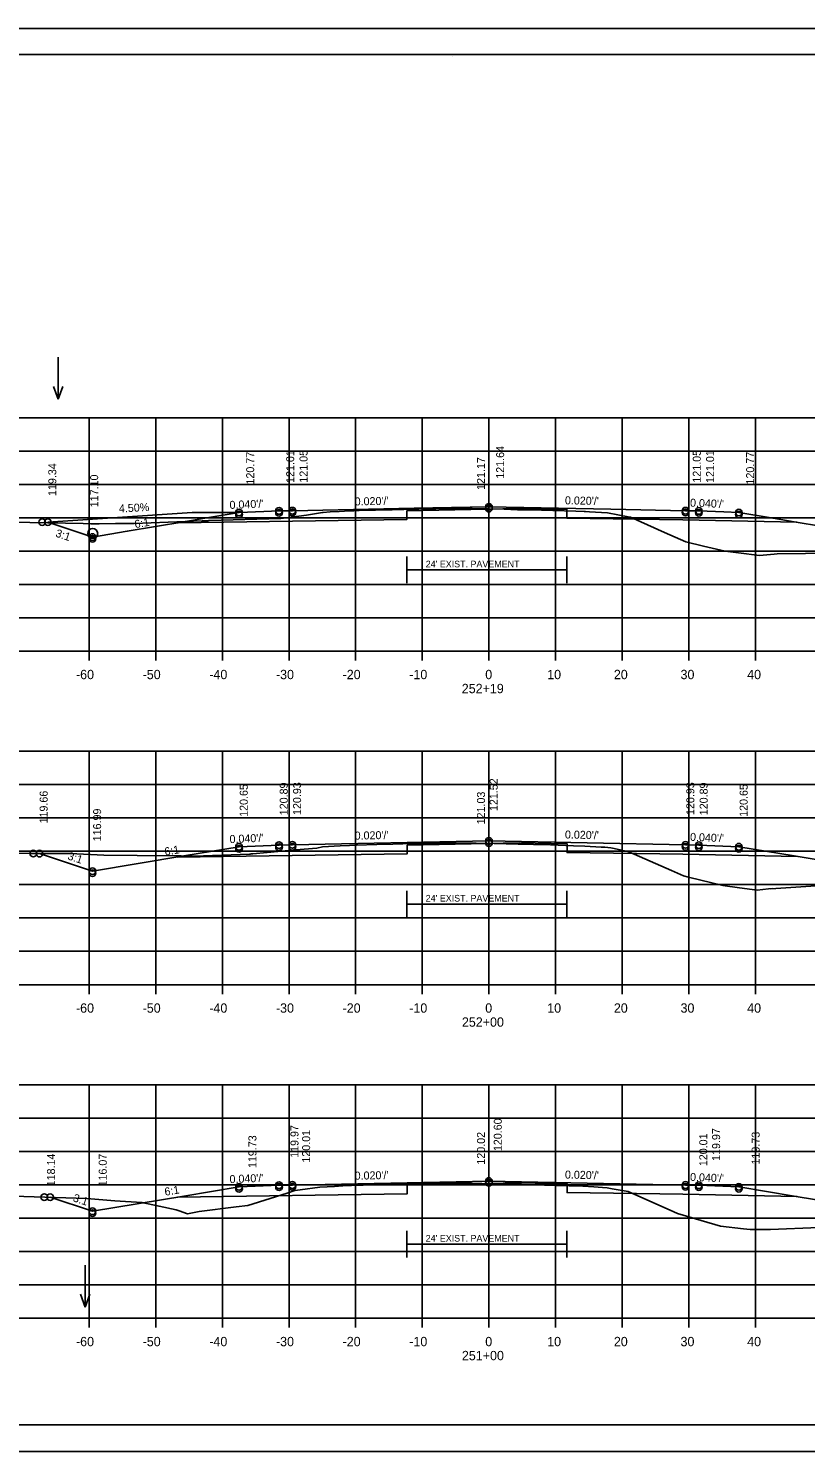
# Model space of a CAD drawing. Extents: x 1175611 to 1176402, y -433344 to -416213.
# Drawn here: x 1175711.9 to 1175828.5, y -421183.3 to -420969.9 of the extents above; entities that cross this region are included whole.
import ezdxf

# ---------------------------------------------------------------- set-up
doc = ezdxf.new("R2010")
doc.units = 0
for name, color, linetype in [('R_Alt Surface', 7, 'Continuous'), ('R_Axis', 7, 'Continuous'), ('R_Axis Annot', 7, 'Continuous'), ('R_Border', 7, 'Continuous'), ('R_Drive', 7, 'Continuous'), ('R_Exist Surface', 7, 'Continuous'), ('R_Fin Surface', 7, 'Continuous'), ('R_Grid', 7, 'Continuous'), ('R_No Plot', 7, 'Continuous'), ('R_Water', 7, 'Continuous'), ('R_Water Annot', 7, 'Continuous'), ('R_Xsect Elev', 7, 'Continuous'), ('R_Xsect Slope', 7, 'Continuous')]:
    doc.layers.add(name, color=color, linetype=linetype)

msp = doc.modelspace()

# ---------------------------------------------------------------- linework, layer by layer
at = {"layer": 'R_Alt Surface'}
for p, q in [((1175768.67, -421051.1), (1175792.67, -421051.1)), ((1175768.67, -421101.2), (1175792.67, -421101.2)), ((1175768.67, -421152.19), (1175792.67, -421152.19))]:
    msp.add_line(p, q, dxfattribs=at)
for points in [[(1175734.32, -421044.03), (1175768.67, -421043.54), (1175768.67, -421042.22), (1175785.47, -421041.88), (1175792.67, -421042.03), (1175792.67, -421043.35), (1175810.04, -421043.61), (1175827.15, -421043.95)], [(1175768.67, -421053.1), (1175768.67, -421049.1)], [(1175792.67, -421053.1), (1175792.67, -421049.1)], [(1175734.21, -421094.15), (1175768.7, -421093.66), (1175768.7, -421092.34), (1175785.5, -421092), (1175792.7, -421092.14), (1175792.7, -421093.47), (1175810.07, -421093.72), (1175827.26, -421094.07)], [(1175768.67, -421103.2), (1175768.67, -421099.2)], [(1175792.67, -421103.2), (1175792.67, -421099.2)], [(1175734.25, -421145.12), (1175768.7, -421144.63), (1175768.7, -421143.31), (1175785.5, -421142.98), (1175792.7, -421143.12), (1175792.7, -421144.44), (1175810.07, -421144.7), (1175827.22, -421145.04)], [(1175768.67, -421154.19), (1175768.67, -421150.19)], [(1175792.67, -421154.19), (1175792.67, -421150.19)]]:
    msp.add_lwpolyline(points, dxfattribs=at)
at = {"layer": 'R_Axis'}
for p, q in [((1175640.97, -421063.28), (1175920.97, -421063.28)), ((1175720.97, -421064.68), (1175720.97, -421063.28)), ((1175730.97, -421064.68), (1175730.97, -421063.28)), ((1175740.97, -421064.68), (1175740.97, -421063.28)), ((1175750.97, -421064.68), (1175750.97, -421063.28)), ((1175760.97, -421064.68), (1175760.97, -421063.28)), ((1175770.97, -421064.68), (1175770.97, -421063.28)), ((1175780.97, -421064.68), (1175780.97, -421063.28)), ((1175790.97, -421064.68), (1175790.97, -421063.28)), ((1175800.97, -421064.68), (1175800.97, -421063.28)), ((1175810.97, -421064.68), (1175810.97, -421063.28)), ((1175820.97, -421064.68), (1175820.97, -421063.28)), ((1175640.97, -421113.28), (1175920.97, -421113.28)), ((1175720.97, -421114.68), (1175720.97, -421113.28)), ((1175730.97, -421114.68), (1175730.97, -421113.28)), ((1175740.97, -421114.68), (1175740.97, -421113.28)), ((1175750.97, -421114.68), (1175750.97, -421113.28)), ((1175760.97, -421114.68), (1175760.97, -421113.28)), ((1175770.97, -421114.68), (1175770.97, -421113.28)), ((1175780.97, -421114.68), (1175780.97, -421113.28)), ((1175790.97, -421114.68), (1175790.97, -421113.28)), ((1175800.97, -421114.68), (1175800.97, -421113.28)), ((1175810.97, -421114.68), (1175810.97, -421113.28)), ((1175820.97, -421114.68), (1175820.97, -421113.28)), ((1175640.97, -421163.28), (1175920.97, -421163.28)), ((1175720.97, -421164.68), (1175720.97, -421163.28)), ((1175730.97, -421164.68), (1175730.97, -421163.28)), ((1175740.97, -421164.68), (1175740.97, -421163.28)), ((1175750.97, -421164.68), (1175750.97, -421163.28)), ((1175760.97, -421164.68), (1175760.97, -421163.28)), ((1175770.97, -421164.68), (1175770.97, -421163.28)), ((1175780.97, -421164.68), (1175780.97, -421163.28)), ((1175790.97, -421164.68), (1175790.97, -421163.28)), ((1175800.97, -421164.68), (1175800.97, -421163.28)), ((1175810.97, -421164.68), (1175810.97, -421163.28)), ((1175820.97, -421164.68), (1175820.97, -421163.28))]:
    msp.add_line(p, q, dxfattribs=at)
at = {"layer": 'R_Border'}
for p, q in [((1175622.97, -420973.82), (1175939.15, -420973.82)), ((1175775.49, -420974.08), (1175775.49, -420974.08)), ((1175775.49, -420974.08), (1175775.49, -420974.08)), ((1175939.15, -421179.28), (1175622.97, -421179.28))]:
    msp.add_line(p, q, dxfattribs=at)
at = {"layer": 'R_Drive'}
for p, q in [((1175736.44, -421042.5), (1175714.8, -421043.94)), ((1175743.47, -421042.5), (1175736.44, -421042.5))]:
    msp.add_line(p, q, dxfattribs=at)
at = {"layer": 'R_Exist Surface'}
for points in [[(1175709.42, -421043.92), (1175720.09, -421044.15), (1175721.25, -421044.18), (1175722.5, -421044.17), (1175724.92, -421044.13), (1175727.72, -421044.12), (1175737.95, -421043.75), (1175738.77, -421043.73), (1175738.95, -421043.71), (1175739, -421043.71), (1175749.75, -421043.4), (1175753.59, -421042.88), (1175756, -421042.51), (1175756.08, -421042.49), (1175757.13, -421042.41), (1175758.49, -421042.35), (1175760.12, -421042.26), (1175760.71, -421042.23), (1175761.48, -421042.21), (1175766.43, -421042.08), (1175768.18, -421042.03), (1175769.69, -421042.01), (1175770.44, -421042), (1175771.43, -421041.96), (1175771.8, -421041.95), (1175772.32, -421041.94), (1175773.01, -421041.92), (1175776.87, -421041.9), (1175778.43, -421041.9), (1175783.26, -421042.01), (1175785.24, -421042.07), (1175787.09, -421042.11), (1175794.01, -421042.3), (1175795.25, -421042.34), (1175795.44, -421042.35), (1175796.04, -421042.39), (1175798.74, -421042.55), (1175801.85, -421043.12), (1175802.2, -421043.2), (1175807.33, -421045.49), (1175810.52, -421046.9), (1175813.18, -421047.54), (1175816.39, -421048.27), (1175818.42, -421048.53), (1175821.57, -421048.96), (1175823.75, -421048.73), (1175824.2, -421048.68)], [(1175824.2, -421048.68), (1175858.06, -421048.31), (1175859.82, -421048.38), (1175861.83, -421048.42), (1175869.52, -421048.15), (1175869.77, -421048.14), (1175875.61, -421048.24), (1175896.58, -421048.59), (1175904.8, -421048.59), (1175920.97, -421048.58)], [(1175703.72, -421093.52), (1175712.22, -421093.63), (1175718.13, -421093.62), (1175723.17, -421093.87), (1175728.19, -421093.92), (1175734.81, -421093.98), (1175736.28, -421094.01), (1175736.73, -421094.01), (1175745.03, -421093.7), (1175745.15, -421093.7), (1175745.27, -421093.68), (1175745.55, -421093.65), (1175751.99, -421093.08), (1175755.16, -421092.79), (1175756.01, -421092.63), (1175758.67, -421092.46), (1175760.06, -421092.39), (1175761.1, -421092.35), (1175764.17, -421092.27), (1175766.53, -421092.21), (1175769.53, -421092.13), (1175770.55, -421092.12), (1175771.05, -421092.11), (1175771.73, -421092.1), (1175772.67, -421092.08), (1175775.1, -421092.05), (1175777.22, -421092.05), (1175779.06, -421092.06), (1175781.77, -421092.13), (1175785.35, -421092.23), (1175787.65, -421092.27), (1175790.2, -421092.33), (1175793.63, -421092.44), (1175795.34, -421092.5), (1175797.81, -421092.64), (1175798.36, -421092.67), (1175798.78, -421092.69), (1175799.26, -421092.78), (1175799.74, -421092.88), (1175801.95, -421093.36), (1175808.37, -421096.17), (1175810.16, -421096.95), (1175810.91, -421097.14), (1175816.07, -421098.42), (1175818.57, -421098.76), (1175821.19, -421099.13), (1175822.92, -421098.92), (1175823.48, -421098.85)], [(1175823.27, -421098.89), (1175833.76, -421098.19), (1175859.95, -421098.36), (1175863.53, -421098.46), (1175866.01, -421098.48), (1175869.9, -421098.34), (1175884.44, -421098.52), (1175896.73, -421098.7), (1175909.4, -421098.72), (1175920.97, -421098.77)], [(1175703.21, -421144.78), (1175720.64, -421145.31), (1175724.86, -421145.66), (1175728.91, -421145.91), (1175731.47, -421146.49), (1175734.02, -421147.05), (1175734.5, -421147.2), (1175735.75, -421147.61), (1175736.98, -421147.38), (1175737.51, -421147.28), (1175743.04, -421146.57), (1175744.78, -421146.36), (1175750.68, -421144.54), (1175751.83, -421144.14), (1175752.62, -421144.04), (1175755.61, -421143.61), (1175757.79, -421143.51), (1175759.67, -421143.4), (1175759.81, -421143.4), (1175760.35, -421143.37), (1175763.83, -421143.27), (1175765.59, -421143.21), (1175767.7, -421143.18), (1175768.29, -421143.17), (1175769.95, -421143.13), (1175770.31, -421143.12), (1175771.31, -421143.09), (1175771.64, -421143.08), (1175772.9, -421143.05), (1175774.27, -421143.05), (1175778.35, -421143.04), (1175779.91, -421143.08), (1175784.91, -421143.21), (1175785.29, -421143.23), (1175785.83, -421143.24), (1175789.31, -421143.31), (1175790.91, -421143.36), (1175795.04, -421143.5), (1175796.68, -421143.6), (1175797.98, -421143.68), (1175798.68, -421143.73), (1175799.43, -421143.87), (1175801.83, -421144.3), (1175808.71, -421147.31), (1175809.28, -421147.56), (1175812.79, -421148.62), (1175815.71, -421149.5), (1175819.16, -421149.88), (1175820.18, -421150), (1175821.75, -421150), (1175823.23, -421150)], [(1175823.23, -421150), (1175852.22, -421148.78), (1175855.84, -421149.27), (1175858.64, -421149.41), (1175859.02, -421149.46), (1175861.12, -421149.46), (1175890.77, -421149.54), (1175920.97, -421149.73)]]:
    msp.add_lwpolyline(points, dxfattribs=at)
at = {"layer": 'R_Fin Surface'}
for points in [[(1175714.8, -421043.94), (1175719.72, -421045.58), (1175721.47, -421046.17), (1175726.69, -421045.3), (1175735.2, -421043.88), (1175738.34, -421043.36), (1175743.47, -421042.5), (1175747.19, -421042.35), (1175749.47, -421042.26), (1175750.23, -421042.25), (1175751.47, -421042.22), (1175769.76, -421041.86), (1175780.97, -421041.63), (1175799.26, -421042), (1175810.47, -421042.22), (1175811.23, -421042.24), (1175812.47, -421042.26), (1175816.19, -421042.41), (1175818.47, -421042.5), (1175823.6, -421043.36), (1175826.75, -421043.88), (1175835.26, -421045.3), (1175840.47, -421046.17), (1175847.25, -421048.43)], [(1175713.53, -421093.63), (1175721.47, -421096.27), (1175735.2, -421093.98), (1175743.47, -421092.6), (1175749.47, -421092.36), (1175751.47, -421092.32), (1175780.97, -421091.73), (1175810.47, -421092.32), (1175812.47, -421092.36), (1175818.47, -421092.6), (1175826.75, -421093.98), (1175840.47, -421096.27), (1175846.51, -421098.28)], [(1175715.15, -421145.14), (1175721.47, -421147.25), (1175735.2, -421144.97), (1175743.47, -421143.59), (1175749.47, -421143.35), (1175751.47, -421143.31), (1175780.97, -421142.72), (1175810.47, -421143.31), (1175812.47, -421143.35), (1175818.47, -421143.59), (1175826.75, -421144.97), (1175840.47, -421147.25), (1175849.03, -421150.11), (1175852.79, -421148.85)]]:
    msp.add_lwpolyline(points, dxfattribs=at)
at = {"layer": 'R_Grid'}
for p, q in [((1175640.97, -421028.28), (1175920.97, -421028.28)), ((1175640.97, -421028.28), (1175920.97, -421028.28)), ((1175720.97, -421063.28), (1175720.97, -421028.28)), ((1175720.97, -421063.28), (1175720.97, -421028.28)), ((1175730.97, -421063.28), (1175730.97, -421028.28)), ((1175730.97, -421063.28), (1175730.97, -421028.28)), ((1175740.97, -421063.28), (1175740.97, -421028.28)), ((1175740.97, -421063.28), (1175740.97, -421028.28)), ((1175750.97, -421063.28), (1175750.97, -421028.28)), ((1175750.97, -421063.28), (1175750.97, -421028.28)), ((1175760.97, -421063.28), (1175760.97, -421028.28)), ((1175760.97, -421063.28), (1175760.97, -421028.28)), ((1175770.97, -421063.28), (1175770.97, -421028.28)), ((1175770.97, -421063.28), (1175770.97, -421028.28)), ((1175780.97, -421063.28), (1175780.97, -421028.28)), ((1175780.97, -421063.28), (1175780.97, -421028.28)), ((1175790.97, -421063.28), (1175790.97, -421028.28)), ((1175790.97, -421063.28), (1175790.97, -421028.28)), ((1175800.97, -421063.28), (1175800.97, -421028.28)), ((1175800.97, -421063.28), (1175800.97, -421028.28)), ((1175810.97, -421063.28), (1175810.97, -421028.28)), ((1175810.97, -421063.28), (1175810.97, -421028.28)), ((1175820.97, -421063.28), (1175820.97, -421028.28)), ((1175820.97, -421063.28), (1175820.97, -421028.28)), ((1175640.97, -421033.28), (1175920.97, -421033.28)), ((1175640.97, -421033.28), (1175920.97, -421033.28)), ((1175640.97, -421038.28), (1175920.97, -421038.28)), ((1175640.97, -421038.28), (1175920.97, -421038.28)), ((1175640.97, -421043.28), (1175920.97, -421043.28)), ((1175640.97, -421043.28), (1175920.97, -421043.28)), ((1175640.97, -421048.28), (1175920.97, -421048.28)), ((1175640.97, -421048.28), (1175920.97, -421048.28)), ((1175640.97, -421053.28), (1175920.97, -421053.28)), ((1175640.97, -421053.28), (1175920.97, -421053.28)), ((1175640.97, -421058.28), (1175920.97, -421058.28)), ((1175640.97, -421058.28), (1175920.97, -421058.28)), ((1175640.97, -421063.28), (1175920.97, -421063.28)), ((1175640.97, -421063.28), (1175920.97, -421063.28)), ((1175640.97, -421078.28), (1175920.97, -421078.28)), ((1175640.97, -421078.28), (1175920.97, -421078.28)), ((1175720.97, -421113.28), (1175720.97, -421078.28)), ((1175720.97, -421113.28), (1175720.97, -421078.28)), ((1175730.97, -421113.28), (1175730.97, -421078.28)), ((1175730.97, -421113.28), (1175730.97, -421078.28)), ((1175740.97, -421113.28), (1175740.97, -421078.28)), ((1175740.97, -421113.28), (1175740.97, -421078.28)), ((1175750.97, -421113.28), (1175750.97, -421078.28)), ((1175750.97, -421113.28), (1175750.97, -421078.28)), ((1175760.97, -421113.28), (1175760.97, -421078.28)), ((1175760.97, -421113.28), (1175760.97, -421078.28)), ((1175770.97, -421113.28), (1175770.97, -421078.28)), ((1175770.97, -421113.28), (1175770.97, -421078.28)), ((1175780.97, -421113.28), (1175780.97, -421078.28)), ((1175780.97, -421113.28), (1175780.97, -421078.28)), ((1175790.97, -421113.28), (1175790.97, -421078.28)), ((1175790.97, -421113.28), (1175790.97, -421078.28)), ((1175800.97, -421113.28), (1175800.97, -421078.28)), ((1175800.97, -421113.28), (1175800.97, -421078.28)), ((1175810.97, -421113.28), (1175810.97, -421078.28)), ((1175810.97, -421113.28), (1175810.97, -421078.28)), ((1175820.97, -421113.28), (1175820.97, -421078.28)), ((1175820.97, -421113.28), (1175820.97, -421078.28)), ((1175640.97, -421083.28), (1175920.97, -421083.28)), ((1175640.97, -421083.28), (1175920.97, -421083.28)), ((1175640.97, -421088.28), (1175920.97, -421088.28)), ((1175640.97, -421088.28), (1175920.97, -421088.28)), ((1175640.97, -421093.28), (1175920.97, -421093.28)), ((1175640.97, -421093.28), (1175920.97, -421093.28)), ((1175640.97, -421098.28), (1175920.97, -421098.28)), ((1175640.97, -421098.28), (1175920.97, -421098.28)), ((1175640.97, -421103.28), (1175920.97, -421103.28)), ((1175640.97, -421103.28), (1175920.97, -421103.28)), ((1175640.97, -421108.28), (1175920.97, -421108.28)), ((1175640.97, -421108.28), (1175920.97, -421108.28)), ((1175640.97, -421113.28), (1175920.97, -421113.28)), ((1175640.97, -421113.28), (1175920.97, -421113.28)), ((1175640.97, -421128.28), (1175920.97, -421128.28)), ((1175640.97, -421128.28), (1175920.97, -421128.28)), ((1175720.97, -421163.28), (1175720.97, -421128.28)), ((1175720.97, -421163.28), (1175720.97, -421128.28)), ((1175730.97, -421163.28), (1175730.97, -421128.28)), ((1175730.97, -421163.28), (1175730.97, -421128.28)), ((1175740.97, -421163.28), (1175740.97, -421128.28)), ((1175740.97, -421163.28), (1175740.97, -421128.28)), ((1175750.97, -421163.28), (1175750.97, -421128.28)), ((1175750.97, -421163.28), (1175750.97, -421128.28)), ((1175760.97, -421163.28), (1175760.97, -421128.28)), ((1175760.97, -421163.28), (1175760.97, -421128.28)), ((1175770.97, -421163.28), (1175770.97, -421128.28)), ((1175770.97, -421163.28), (1175770.97, -421128.28)), ((1175780.97, -421163.28), (1175780.97, -421128.28)), ((1175780.97, -421163.28), (1175780.97, -421128.28)), ((1175790.97, -421163.28), (1175790.97, -421128.28)), ((1175790.97, -421163.28), (1175790.97, -421128.28)), ((1175800.97, -421163.28), (1175800.97, -421128.28)), ((1175800.97, -421163.28), (1175800.97, -421128.28)), ((1175810.97, -421163.28), (1175810.97, -421128.28)), ((1175810.97, -421163.28), (1175810.97, -421128.28)), ((1175820.97, -421163.28), (1175820.97, -421128.28)), ((1175820.97, -421163.28), (1175820.97, -421128.28)), ((1175640.97, -421133.28), (1175920.97, -421133.28)), ((1175640.97, -421133.28), (1175920.97, -421133.28)), ((1175640.97, -421138.28), (1175920.97, -421138.28)), ((1175640.97, -421138.28), (1175920.97, -421138.28)), ((1175640.97, -421143.28), (1175920.97, -421143.28)), ((1175640.97, -421143.28), (1175920.97, -421143.28)), ((1175640.97, -421148.28), (1175920.97, -421148.28)), ((1175640.97, -421148.28), (1175920.97, -421148.28)), ((1175640.97, -421153.28), (1175920.97, -421153.28)), ((1175640.97, -421153.28), (1175920.97, -421153.28)), ((1175640.97, -421158.28), (1175920.97, -421158.28)), ((1175640.97, -421158.28), (1175920.97, -421158.28)), ((1175640.97, -421163.28), (1175920.97, -421163.28)), ((1175640.97, -421163.28), (1175920.97, -421163.28))]:
    msp.add_line(p, q, dxfattribs=at)
at = {"layer": 'R_No Plot'}
for p, q in [((1175610.57, -420969.93), (1175943.91, -420969.93)), ((1175610.57, -421183.26), (1175943.91, -421183.26))]:
    msp.add_line(p, q, dxfattribs=at)
msp.add_lwpolyline([(1175610.57, -420969.93), (1175943.91, -420969.93), (1175943.91, -421183.27), (1175610.57, -421183.27)], close=True, dxfattribs=at)
for centre in [(1175743.47, -421042.5), (1175743.47, -421042.78), (1175749.47, -421042.26), (1175749.47, -421042.54), (1175751.47, -421042.22), (1175751.47, -421042.5), (1175780.97, -421041.63), (1175780.97, -421041.91), (1175810.47, -421042.22), (1175810.47, -421042.5), (1175812.47, -421042.26), (1175812.47, -421042.54), (1175818.47, -421042.5), (1175818.47, -421042.78), (1175713.94, -421043.93), (1175714.8, -421043.94), (1175714.8, -421043.94), (1175721.47, -421046.17), (1175721.47, -421046.44), (1175743.47, -421092.6), (1175749.47, -421092.36), (1175751.47, -421092.32), (1175751.47, -421092.63), (1175780.97, -421091.73), (1175780.97, -421092.04), (1175810.47, -421092.32), (1175810.47, -421092.63), (1175812.47, -421092.36), (1175818.47, -421092.6), (1175712.61, -421093.62), (1175713.53, -421093.63), (1175713.53, -421093.63), (1175743.47, -421092.91), (1175749.47, -421092.67), (1175812.47, -421092.67), (1175818.47, -421092.91), (1175721.47, -421096.27), (1175721.47, -421096.57), (1175743.47, -421143.59), (1175743.47, -421143.86), (1175749.47, -421143.35), (1175749.47, -421143.62), (1175751.47, -421143.31), (1175751.47, -421143.58), (1175780.97, -421142.72), (1175780.97, -421142.99), (1175810.47, -421143.31), (1175810.47, -421143.58), (1175812.47, -421143.35), (1175812.47, -421143.62), (1175818.47, -421143.59), (1175818.47, -421143.86), (1175714.26, -421145.12), (1175715.15, -421145.14), (1175715.15, -421145.14), (1175721.47, -421147.25), (1175721.47, -421147.52)]:
    msp.add_circle(centre, 0.5, dxfattribs=at)
at = {"layer": 'R_Water'}
msp.add_circle((1175721.52, -421045.64), 0.75, dxfattribs=at)
at = {"layer": 'R_Water Annot'}
for p, q in [((1175716.35, -421019.22), (1175716.35, -421025.51)), ((1175716.35, -421025.51), (1175715.65, -421023.59)), ((1175716.35, -421025.51), (1175717.05, -421023.59)), ((1175720.41, -421155.32), (1175720.41, -421161.61)), ((1175720.41, -421161.61), (1175719.71, -421159.68)), ((1175720.41, -421161.61), (1175721.11, -421159.68))]:
    msp.add_line(p, q, dxfattribs=at)

# ---------------------------------------------------------------- texts
at = {"layer": 'R_Alt Surface'}
for p in [(1175771.48, -421050.72), (1175771.48, -421100.82), (1175771.48, -421151.8)]:
    msp.add_text("24' EXIST. PAVEMENT", height=1, dxfattribs=at).set_placement(p)
at = {"layer": 'R_Axis Annot'}
for s, p in [('-60', (1175719.01, -421067.48)), ('-50', (1175729.01, -421067.48)), ('-40', (1175739.01, -421067.48)), ('-30', (1175749.01, -421067.48)), ('-20', (1175759.01, -421067.48)), ('-10', (1175769.01, -421067.48)), ('0', (1175780.41, -421067.48)), ('10', (1175789.71, -421067.48)), ('20', (1175799.71, -421067.48)), ('30', (1175809.71, -421067.48)), ('40', (1175819.71, -421067.48)), ('252+19', (1175776.89, -421069.58)), ('-60', (1175719.01, -421117.48)), ('-50', (1175729.01, -421117.48)), ('-40', (1175739.01, -421117.48)), ('-30', (1175749.01, -421117.48)), ('-20', (1175759.01, -421117.48)), ('-10', (1175769.01, -421117.48)), ('0', (1175780.41, -421117.48)), ('10', (1175789.71, -421117.48)), ('20', (1175799.71, -421117.48)), ('30', (1175809.71, -421117.48)), ('40', (1175819.71, -421117.48)), ('252+00', (1175776.91, -421119.58)), ('-60', (1175719.01, -421167.48)), ('-50', (1175729.01, -421167.48)), ('-40', (1175739.01, -421167.48)), ('-30', (1175749.01, -421167.48)), ('-20', (1175759.01, -421167.48)), ('-10', (1175769.01, -421167.48)), ('0', (1175780.41, -421167.48)), ('10', (1175789.71, -421167.48)), ('20', (1175799.71, -421167.48)), ('30', (1175809.71, -421167.48)), ('40', (1175819.71, -421167.48)), ('251+00', (1175776.91, -421169.58))]:
    msp.add_text(s, height=1.4, dxfattribs=at).set_placement(p)
at = {"layer": 'R_Drive'}
msp.add_text('4.50%', height=1.2, rotation=2.908, dxfattribs=at).set_placement((1175725.48, -421042.5))
at = {"layer": 'R_Xsect Elev'}
for s, p in [('120.77', (1175745.75, -421038.3)), ('121.01', (1175751.75, -421038.06)), ('121.05', (1175753.75, -421038.02)), ('121.17', (1175780.37, -421039.11)), ('121.64', (1175783.25, -421037.43)), ('121.05', (1175812.75, -421038.02)), ('121.01', (1175814.75, -421038.06)), ('120.77', (1175820.75, -421038.3)), ('119.34', (1175716.06, -421040.02)), ('117.10', (1175722.34, -421041.71)), ('120.65', (1175744.78, -421088.12)), ('120.89', (1175750.78, -421087.88)), ('120.93', (1175752.78, -421087.84)), ('121.52', (1175782.28, -421087.25)), ('120.93', (1175811.78, -421087.84)), ('120.89', (1175813.78, -421087.88)), ('120.65', (1175819.78, -421088.12)), ('119.66', (1175714.76, -421089.11)), ('121.03', (1175780.37, -421089.25)), ('116.99', (1175722.78, -421091.79)), ('119.97', (1175752.39, -421139.24)), ('120.60', (1175782.89, -421138.23)), ('119.73', (1175746.08, -421140.77)), ('120.01', (1175754.14, -421139.96)), ('120.02', (1175780.37, -421140.26)), ('120.01', (1175813.73, -421140.49)), ('119.97', (1175815.65, -421139.7)), ('119.73', (1175821.58, -421140.24)), ('118.14', (1175715.87, -421143.51)), ('116.07', (1175723.62, -421143.53))]:
    msp.add_text(s, height=1.2, rotation=90, dxfattribs=at).set_placement(p)
at = {"layer": 'R_Xsect Slope'}
for s, rotation, p in [("0.040'/'", 2.2906, (1175742.07, -421041.96)), ("0.020'/'", 1.1458, (1175760.83, -421041.44)), ("0.020'/'", 358.8542, (1175792.36, -421041.26)), ("0.040'/'", 357.7094, (1175811.12, -421041.61)), ('3:1', 341.5651, (1175715.84, -421046.08)), ('6:1', 9.4623, (1175727.89, -421044.85)), ("0.040'/'", 2.2906, (1175742.07, -421092.06)), ("0.020'/'", 1.1458, (1175760.83, -421091.54)), ("0.020'/'", 358.8542, (1175792.36, -421091.36)), ("0.040'/'", 357.7094, (1175811.12, -421091.71)), ('3:1', 341.5651, (1175717.66, -421094.47)), ('6:1', 9.4623, (1175732.39, -421093.94)), ("0.020'/'", 1.1458, (1175760.83, -421142.52)), ("0.020'/'", 358.8542, (1175792.36, -421142.34)), ("0.040'/'", 2.2906, (1175742.07, -421143.04)), ("0.040'/'", 357.7094, (1175811.12, -421142.69)), ('3:1', 341.5651, (1175718.47, -421145.72)), ('6:1', 9.4623, (1175732.39, -421144.93))]:
    msp.add_text(s, height=1.2, rotation=rotation, dxfattribs=at).set_placement(p)

doc.saveas('drawing.dxf')
